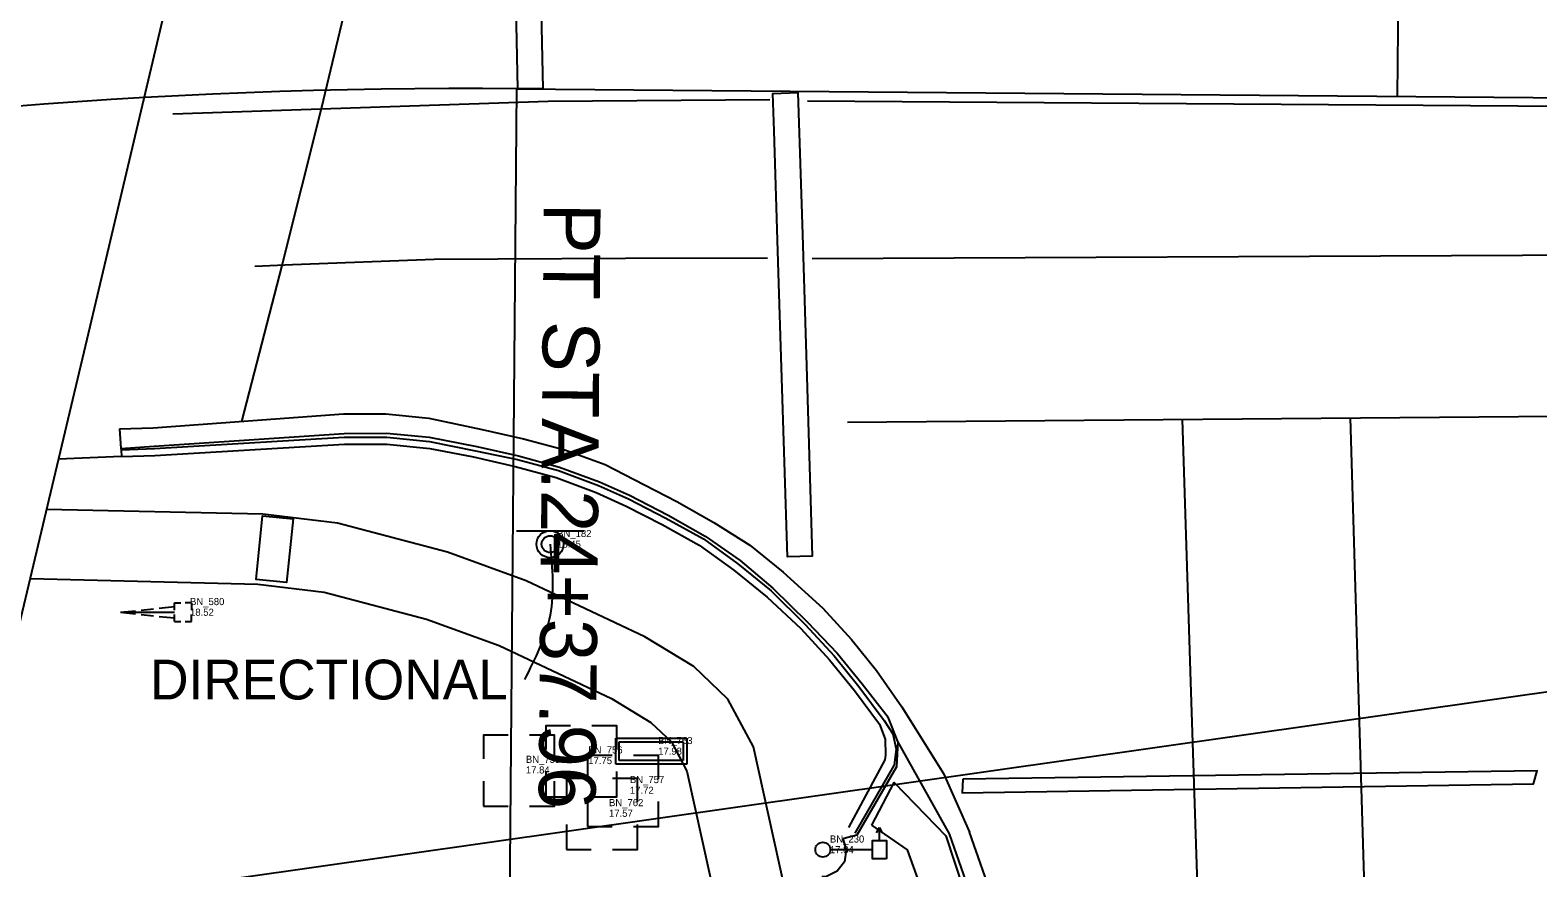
# Model space of a CAD drawing. Extents: x 509744 to 512285, y 1314862 to 1316822.
# Drawn here: x 511071.2 to 511177.3, y 1315566.8 to 1315625.7 of the extents above; entities that cross this region are included whole.
import ezdxf

# ---------------------------------------------------------------- set-up
doc = ezdxf.new("R2010")
doc.units = 0
for name, color, linetype in [('BaselineSurvey', 7, 'Continuous'), ('CGBack_ep', 7, 'Continuous'), ('CGep_ep', 7, 'Continuous'), ('CGFace_ep', 7, 'Continuous'), ('CurbRampWarning_ep', 7, 'Continuous'), ('ElecAer_ep', 7, 'Continuous'), ('JunctBox_ep', 7, 'Continuous'), ('PavtAsphalt_ep', 7, 'Continuous'), ('PavtBreak_ep', 7, 'Continuous'), ('PMRK_ep', 7, 'Continuous'), ('PullBox_ep', 7, 'Continuous'), ('RailroadSgnalG_ep', 7, 'Continuous'), ('RailroadXing_ep', 7, 'Continuous'), ('SidewalkBack_ep', 7, 'Continuous'), ('SidewalkFront_ep', 7, 'Continuous'), ('SignalSupport_ep', 7, 'Continuous'), ('SignSingle_ep', 7, 'Continuous'), ('TextElevLabel', 7, 'Continuous'), ('TextPtLabel', 7, 'Continuous'), ('TextTopoLabel_ep', 7, 'Continuous')]:
    doc.layers.add(name, color=color, linetype=linetype)

msp = doc.modelspace()

# ---------------------------------------------------------------- linework, layer by layer
at = {"layer": 'BaselineSurvey'}
for p, q in [((511167.43, 1315621.1), (511167.5, 1315629.1)), ((511105.4, 1315621.62), (511104.89, 1315562.2)), ((511105.4, 1315621.62), (512116.98, 1315613.07))]:
    msp.add_line(p, q, dxfattribs=at)
msp.add_arc((511101.97, 1315216.26), 405.38, 89.5155, 110.9887, dxfattribs=at)
msp.add_arc((511101.97, 1315216.26), 405.38, 89.5155, 110.9887, dxfattribs=at)
at = {"layer": 'CGBack_ep'}
msp.add_line((511131.33, 1315574.38), (511128.77, 1315569.62), dxfattribs=at)
for points in [[(511077.6, 1315595.73), (511079.96, 1315595.82), (511093.29, 1315596.61), (511096.29, 1315596.62), (511099.3, 1315596.3), (511102.38, 1315595.71), (511105.31, 1315595.04), (511108.21, 1315594.26), (511111.02, 1315593.2), (511113.12, 1315592.25), (511115.66, 1315590.96), (511118.27, 1315589.49), (511120.71, 1315587.74), (511123.06, 1315585.85), (511125.42, 1315583.63), (511127.45, 1315581.42), (511129.21, 1315579.27), (511130.95, 1315576.91)], [(511130.95, 1315576.91), (511131.36, 1315575.85), (511131.39, 1315574.71), (511131.33, 1315574.38)]]:
    msp.add_lwpolyline(points, dxfattribs=at)
at = {"layer": 'CGep_ep'}
for points in [[(511077.56, 1315596.31), (511079.91, 1315596.48), (511093.27, 1315597.35), (511096.26, 1315597.39), (511099.27, 1315597.11), (511102.61, 1315596.45), (511105.54, 1315595.78), (511108.44, 1315595), (511111.26, 1315593.96), (511113.36, 1315593.01), (511116.08, 1315591.62), (511118.68, 1315590.13), (511121.15, 1315588.42), (511123.46, 1315586.48), (511125.9, 1315584.08), (511127.97, 1315581.91), (511129.73, 1315579.75), (511131.57, 1315577.39)], [(511135.89, 1315569.18), (511132.26, 1315575.67), (511131.57, 1315577.39)], [(511148.54, 1315234.37), (511145, 1315284.26), (511141.44, 1315334.13), (511137.92, 1315384), (511134.34, 1315433.91), (511134.19, 1315440.39), (511135.37, 1315450.55), (511142.1, 1315489.79), (511142.41, 1315499.79), (511142.08, 1315509.63), (511141.71, 1315519.62), (511140.55, 1315549.58), (511139.35, 1315559.27), (511135.89, 1315569.18)]]:
    msp.add_lwpolyline(points, dxfattribs=at)
at = {"layer": 'CGFace_ep'}
msp.add_line((511131.97, 1315574), (511129.22, 1315569.23), dxfattribs=at)
for points in [[(511077.57, 1315596.21), (511079.93, 1315596.3), (511093.27, 1315597.1), (511096.27, 1315597.11), (511099.28, 1315596.79), (511102.52, 1315596.15), (511105.47, 1315595.54), (511108.36, 1315594.76), (511111.18, 1315593.71), (511113.28, 1315592.75), (511115.93, 1315591.4), (511118.56, 1315589.94), (511120.99, 1315588.18), (511123.34, 1315586.29), (511125.73, 1315583.92), (511127.76, 1315581.71), (511129.51, 1315579.55), (511131.29, 1315577.17)], [(511131.29, 1315577.17), (511131.89, 1315576.23), (511132.13, 1315575.14), (511131.98, 1315574.03), (511131.97, 1315574)]]:
    msp.add_lwpolyline(points, dxfattribs=at)
at = {"layer": 'CurbRampWarning_ep'}
for points in [[(511089.68, 1315591.35), (511089.22, 1315586.88), (511087.08, 1315587.09), (511087.53, 1315591.57)], [(511130.43, 1315569.79), (511131.99, 1315572.8), (511135.63, 1315569.04), (511138.05, 1315561.69), (511135.76, 1315560.17), (511132.94, 1315568.05)]]:
    msp.add_lwpolyline(points, close=True, dxfattribs=at)
at = {"layer": 'ElecAer_ep'}
msp.add_line((511019.6, 1315556.68), (511243.35, 1315588.47), dxfattribs=at)
at = {"layer": 'JunctBox_ep'}
for p, q in [((511112.39, 1315575.91), (511117.39, 1315575.91)), ((511112.39, 1315574.09), (511112.39, 1315575.91)), ((511112.64, 1315575.66), (511117.14, 1315575.66)), ((511112.64, 1315574.34), (511112.64, 1315575.66)), ((511117.14, 1315575.66), (511117.14, 1315574.34)), ((511117.39, 1315575.91), (511117.39, 1315574.09)), ((511117.39, 1315574.09), (511112.39, 1315574.09)), ((511117.14, 1315574.34), (511112.64, 1315574.34))]:
    msp.add_line(p, q, dxfattribs=at)
at = {"layer": 'PavtAsphalt_ep'}
for points in [[(511077.47, 1315597.68), (511079.83, 1315597.75), (511093.22, 1315598.74), (511096.22, 1315598.74), (511099.23, 1315598.43), (511102.98, 1315597.64), (511105.91, 1315596.99), (511108.81, 1315596.21), (511111.64, 1315595.18), (511113.7, 1315594.12), (511116.69, 1315592.57), (511119.29, 1315591.09), (511121.84, 1315589.51), (511124.18, 1315587.61), (511126.96, 1315585.06), (511128.99, 1315582.86), (511130.74, 1315580.69), (511132.53, 1315578.12)], [(511077.47, 1315597.68), (511077.56, 1315596.31), (511077.57, 1315596.21), (511077.6, 1315595.73), (511073.17, 1315595.55)], [(511132.53, 1315578.12), (511135.47, 1315573.44), (511137.29, 1315569.29)], [(511149.72, 1315234.46), (511146.19, 1315284.34), (511142.63, 1315334.21), (511139.11, 1315384.09), (511135.53, 1315433.97), (511135.38, 1315440.34), (511136.54, 1315450.35), (511143.27, 1315489.73), (511143.59, 1315499.72), (511143.25, 1315509.67), (511142.89, 1315519.67), (511141.73, 1315549.64), (511140.73, 1315559.54), (511137.29, 1315569.29)]]:
    msp.add_lwpolyline(points, dxfattribs=at)
at = {"layer": 'PavtBreak_ep'}
for points in [[(511085, 1315642.52), (511097.12, 1315642.69), (511094.65, 1315632.7), (511091.66, 1315620.22), (511088.89, 1315609.19), (511086.06, 1315598.21)], [(511125.89, 1315620.77), (511175.88, 1315620.43), (511225.88, 1315620.09), (511246.07, 1315619.95)], [(511126.23, 1315609.68), (511176.23, 1315609.92), (511201.23, 1315610.04), (511226.23, 1315610.16), (511259.26, 1315610.32)], [(511128.71, 1315598.15), (511178.7, 1315598.58), (511203.7, 1315598.8), (511228.69, 1315599.02), (511243.35, 1315599.15)], [(511153.69, 1315554.9), (511152.88, 1315579.89), (511152.29, 1315598.35)], [(511165.39, 1315555.99), (511164.64, 1315580.98), (511164.12, 1315598.46)]]:
    msp.add_lwpolyline(points, dxfattribs=at)
at = {"layer": 'PMRK_ep'}
msp.add_lwpolyline([(511106.8, 1315643.18), (511107.26, 1315621.65), (511105.51, 1315621.61), (511105.05, 1315643.15)], close=True, dxfattribs=at)
for points in [[(511081.22, 1315619.87), (511107.64, 1315620.75), (511123.24, 1315620.88)], [(511125.21, 1315621.35), (511125.53, 1315611.36), (511125.84, 1315601.36), (511126.23, 1315588.73), (511124.48, 1315588.68), (511123.85, 1315608.67), (511123.54, 1315618.66), (511123.46, 1315621.3), (511125.21, 1315621.35)], [(511123.08, 1315609.71), (511113.08, 1315609.67), (511099.62, 1315609.61), (511089.63, 1315609.22), (511086.99, 1315609.11)], [(511136.83, 1315573.02), (511136.77, 1315572.06), (511176.99, 1315572.7), (511177.25, 1315573.61), (511136.83, 1315573.02)]]:
    msp.add_lwpolyline(points, dxfattribs=at)
at = {"layer": 'PullBox_ep'}
for points in [[(511104.82, 1315576.13), (511103.09, 1315576.13), (511103.09, 1315574.46)], [(511108.08, 1315574.46), (511108.08, 1315576.13), (511106.32, 1315576.13)], [(511109.2, 1315576.79), (511107.47, 1315576.79), (511107.47, 1315575.11)], [(511112.46, 1315575.11), (511112.46, 1315576.79), (511110.7, 1315576.79)], [(511112.14, 1315574.7), (511110.41, 1315574.7), (511110.41, 1315573.03)], [(511115.4, 1315573.03), (511115.4, 1315574.7), (511113.64, 1315574.7)], [(511103.09, 1315572.9), (511103.09, 1315571.13)], [(511106.32, 1315571.13), (511108.08, 1315571.13), (511108.08, 1315572.9)], [(511107.47, 1315573.56), (511107.47, 1315571.79)], [(511110.67, 1315573.08), (511108.93, 1315573.08), (511108.93, 1315571.4)], [(511110.7, 1315571.79), (511112.46, 1315571.79), (511112.46, 1315573.56)], [(511113.93, 1315571.4), (511113.93, 1315573.08), (511112.17, 1315573.08)], [(511107.47, 1315571.79), (511109.2, 1315571.79)], [(511103.09, 1315571.13), (511104.82, 1315571.13)], [(511110.41, 1315571.47), (511110.41, 1315569.7)], [(511113.64, 1315569.7), (511115.4, 1315569.7), (511115.4, 1315571.47)], [(511108.93, 1315569.85), (511108.93, 1315568.08)], [(511110.41, 1315569.7), (511112.14, 1315569.7)], [(511112.17, 1315568.08), (511113.93, 1315568.08), (511113.93, 1315569.85)], [(511108.93, 1315568.08), (511110.67, 1315568.08)]]:
    msp.add_lwpolyline(points, dxfattribs=at)
at = {"layer": 'RailroadSgnalG_ep'}
for p, q in [((511077.53, 1315584.78), (511078.59, 1315584.89)), ((511077.53, 1315584.78), (511078.59, 1315584.66)), ((511077.53, 1315584.78), (511081.33, 1315584.78)), ((511078.99, 1315584.93), (511079.86, 1315585.02)), ((511078.99, 1315584.62), (511079.86, 1315584.53)), ((511080.26, 1315585.06), (511081.33, 1315585.18)), ((511080.26, 1315584.49), (511081.33, 1315584.38)), ((511081.33, 1315584.92), (511081.33, 1315585.43)), ((511081.33, 1315585.43), (511081.78, 1315585.43)), ((511081.33, 1315584.13), (511081.33, 1315584.62)), ((511082.53, 1315585.43), (511082.08, 1315585.43)), ((511082.53, 1315585.43), (511082.53, 1315584.92)), ((511082.53, 1315584.13), (511082.53, 1315584.62)), ((511081.33, 1315584.13), (511081.78, 1315584.13)), ((511082.08, 1315584.13), (511082.53, 1315584.13))]:
    msp.add_line(p, q, dxfattribs=at)
at = {"layer": 'RailroadXing_ep'}
msp.add_lwpolyline([(511069.42, 1315579.69), (511075.18, 1315604.01), (511080.93, 1315628.34), (511086.83, 1315652.67), (511092.53, 1315677), (511098.2, 1315701.32), (511103.96, 1315725.65), (511104.69, 1315728.72), (511102.21, 1315729.32), (511099.84, 1315720.59), (511095.16, 1315721.58), (511093.13, 1315712.97), (511090.62, 1315713.5), (511084.87, 1315689.17), (511079.11, 1315664.85), (511073.35, 1315640.52), (511067.6, 1315616.19), (511061.84, 1315591.86), (511059.51, 1315582.01)], dxfattribs=at)
at = {"layer": 'SidewalkBack_ep'}
msp.add_lwpolyline([(511071.19, 1315587.15), (511087.2, 1315586.76), (511091.87, 1315586.2), (511099.07, 1315584.3), (511104.18, 1315582.43), (511112.1, 1315578.71), (511114.87, 1315577.02), (511116.31, 1315575.65), (511117.4, 1315573.59), (511119.56, 1315563.84), (511121.55, 1315555.99), (511110.65, 1315534.84), (511105.62, 1315524.31), (511101.43, 1315512.25), (511098.32, 1315500.87), (511095.97, 1315488.09), (511094.34, 1315479.2), (511093.9, 1315474.9), (511092.86, 1315460.94), (511092.65, 1315449.97), (511093.66, 1315432.04), (511094.6, 1315420.64), (511096.36, 1315412.04), (511100.18, 1315396.27)], dxfattribs=at)
at = {"layer": 'SidewalkFront_ep'}
msp.add_line((511129.37, 1315569.1), (511128.37, 1315568.84), dxfattribs=at)
for points in [[(511125, 1315562.11), (511122.08, 1315575.31), (511120.29, 1315578.66), (511117.89, 1315580.96), (511114.44, 1315583.05), (511106.08, 1315586.98), (511100.55, 1315589.01), (511092.8, 1315591.06), (511087.55, 1315591.68), (511072.33, 1315592)], [(511132.26, 1315575.67), (511132.15, 1315573.89), (511129.37, 1315569.1)], [(511128.37, 1315568.84), (511128.62, 1315568.05), (511128.49, 1315567.22), (511127.99, 1315566.56), (511127.24, 1315566.19), (511126.91, 1315566.15)]]:
    msp.add_lwpolyline(points, dxfattribs=at)
at = {"layer": 'SignalSupport_ep'}
for p, q in [((511130.75, 1315569.25), (511130.95, 1315569.63)), ((511130.95, 1315568.72), (511130.95, 1315569.63)), ((511130.95, 1315569.63), (511131.15, 1315569.25)), ((511127.5, 1315568.07), (511130.46, 1315568.07))]:
    msp.add_line(p, q, dxfattribs=at)
msp.add_lwpolyline([(511131.45, 1315567.43), (511130.46, 1315567.43), (511130.46, 1315568.72), (511131.45, 1315568.72)], close=True, dxfattribs=at)
msp.add_circle((511126.97, 1315568.07), 0.524, dxfattribs=at)
at = {"layer": 'SignSingle_ep'}
msp.add_line((511105.4, 1315590.52), (511110.15, 1315590.52), dxfattribs=at)
for radius in [0.95, 0.594]:
    msp.add_circle((511107.77, 1315589.57), radius, dxfattribs=at)
at = {"layer": 'TextTopoLabel_ep'}
msp.add_spline([(511107.77, 1315589.57), (511107.77, 1315584.57), (511105.96, 1315580.04)], degree=3, dxfattribs=at)

# ---------------------------------------------------------------- texts
at = {"layer": 'BaselineSurvey'}
msp.add_text('PT STA.24+37.96', height=4, rotation=269.5155, dxfattribs=at).set_placement((511107.33, 1315613.61))
at = {"layer": 'TextElevLabel'}
for s, p in [('18.45', (511108.27, 1315589.32)), ('18.52', (511082.43, 1315584.53)), ('17.98', (511115.38, 1315574.75)), ('17.84', (511106.07, 1315573.43)), ('17.75', (511110.46, 1315574.09)), ('17.72', (511113.39, 1315572)), ('17.57', (511111.92, 1315570.38)), ('17.84', (511127.47, 1315567.82))]:
    msp.add_text(s, height=0.5, dxfattribs=at).set_placement(p)
at = {"layer": 'TextPtLabel'}
for s, p in [('BN_182', (511108.27, 1315590.07)), ('BN_580', (511082.43, 1315585.28)), ('BN_763', (511115.38, 1315575.5)), ('BN_756', (511110.46, 1315574.84)), ('BN_755', (511106.07, 1315574.18)), ('BN_757', (511113.39, 1315572.75)), ('BN_762', (511111.92, 1315571.13)), ('BN_230', (511127.47, 1315568.57))]:
    msp.add_text(s, height=0.5, dxfattribs=at).set_placement(p)
at = {"layer": 'TextTopoLabel_ep'}
msp.add_text('DIRECTIONAL', height=2.8, dxfattribs=at).set_placement((511079.62, 1315578.64))

doc.saveas('drawing.dxf')
